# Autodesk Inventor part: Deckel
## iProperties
Shininess: 20.0
Angle Display Precision: 2
Document Length Units: 11269
Document Angle Units: 11279
Document Time Units: 11290
Document Mass Units: 11283
Document Length Units Precision: 3
Document Angle Units Precision: 2
Created: 2003-02
Part Number: Deckel
Material: S275JR
Document SubType Name: Modellieren
Designer: Administrator
Density: 0.0
Volumn: 0.0
Area: 0.0
PropertySet Name: Model Information
Control State: 0
Master: False
Checked Out: False
Author: Administrator
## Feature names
1. Grundkörper [Revolution]
2. Rundung1 [Fillet]
3. Fase1 [Chamfer]
4. Senkungen [Hole]
